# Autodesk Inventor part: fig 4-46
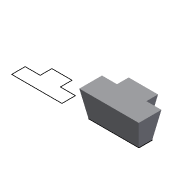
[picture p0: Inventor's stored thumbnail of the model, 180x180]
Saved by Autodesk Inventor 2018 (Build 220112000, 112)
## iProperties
Created: 2004-05
Part Number: fig 4-46
Document SubType Name: Modeling
Designer: CADCIM Technologies
Manufacturer: Standard
Standards Organization: Custom
Density: 1 g/cm^3
Material: Generic
Appearance: Default
Author: CADCIM Technologies
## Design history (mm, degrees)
sketch "Sketch1"
  geometry: L1 (31.783, 34.561)-(31.783, 22.933); L2 (31.783, 22.933)-(16.796, 22.933); L3 (16.796, 22.933)-(16.796, 9.496); L4 (16.796, 9.496)-(66.925, 9.496); L5 (66.925, 9.496)-(66.925, 22.933); L6 (66.925, 22.933)-(51.938, 22.933); L7 (51.938, 22.933)-(51.938, 34.561); L8 (51.938, 34.561)-(31.783, 34.561); L9 (-45.013, 34.561)-(-45.013, 22.933); L10 (-45.013, 22.933)-(-60, 22.933); L11 (-60, 22.933)-(-60, 9.496); L12 (-60, 9.496)-(-9.871, 9.496); L13 (-9.871, 9.496)-(-9.871, 22.933); L14 (-9.871, 22.933)-(-24.858, 22.933); L15 (-24.858, 22.933)-(-24.858, 34.561); L16 (-24.858, 34.561)-(-45.013, 34.561)
  constraints: 32 end point, 10 parallel, 4 equal length, 2 collinear, 2 perpendicular, 2 vertical
extrude "Extrusion2" new body sketch "Sketch1" distance "d2" = 26; taper "d3" = 10 deg
body "Solid2"
